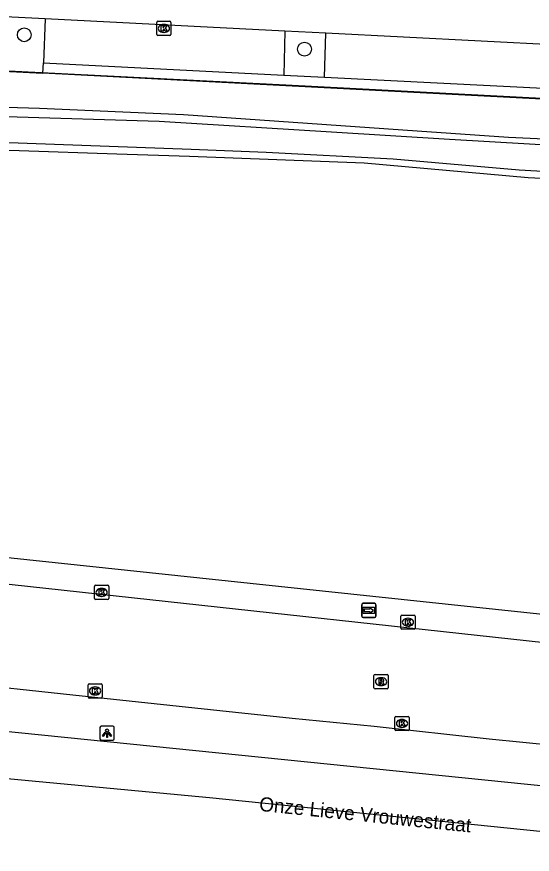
# Model space of a CAD drawing. Extents: x 161761 to 162722, y 384793 to 385405.
# Drawn here: x 162200.7 to 162237, y 384831.7 to 384890.8 of the extents above; entities that cross this region are included whole.
import ezdxf

# ---------------------------------------------------------------- set-up
doc = ezdxf.new("R2010")
doc.units = 0
for name, color, linetype in [('IMGEO_Boom', 7, 'Continuous'), ('IMGEO_Groenvoorziening', 7, 'Continuous'), ('IMGEO_Hek', 7, 'Continuous'), ('IMGEO_Kolk', 7, 'Continuous'), ('IMGEO_Lichtpunt', 7, 'Continuous'), ('IMGEO_Openbare_ruimte_label', 7, 'Continuous'), ('IMGEO_Parkeervlak_open', 7, 'Continuous'), ('IMGEO_Rijbaan_lokaal_open', 7, 'Continuous'), ('IMGEO_Rijbaan_regionaal_gesloten', 7, 'Continuous'), ('IMGEO_Rioolput', 7, 'Continuous'), ('IMGEO_Voetpad_open', 7, 'Continuous'), ('IMGEO_Waterloop', 7, 'Continuous'), ('IMGEO_Wegwijzer', 7, 'Continuous')]:
    doc.layers.add(name, color=color, linetype=linetype)

msp = doc.modelspace()

# ---------------------------------------------------------------- linework, layer by layer
at = {"layer": 'IMGEO_Boom'}
for centre in [(162201.199, 384889.51), (162220.962, 384888.492)]:
    msp.add_circle(centre, 0.489, dxfattribs=at)
at = {"layer": 'IMGEO_Groenvoorziening'}
for points in [[(162202.512, 384886.81), (162202.549, 384887.54)], [(162199.714, 384886.951), (162202.512, 384886.81)], [(162252.154, 384884.215), (162202.512, 384886.81)], [(162219.5, 384886.656), (162222.369, 384886.527)], [(162248.554, 384881.672), (162249.962, 384881.466), (162250.32, 384880.598), (162250.275, 384880.55), (162250.287, 384880.144), (162250.307, 384879.464), (162249.414, 384879.031), (162246.63, 384878.91), (162236.754, 384879.403), (162225.179, 384880.444), (162212.852, 384880.929), (162207.717, 384881.092), (162200.834, 384881.31), (162198.516, 384881.379), (162197.714, 384882.949), (162198.335, 384884.441), (162202.271, 384884.337), (162212.44, 384883.884), (162228.906, 384882.734), (162235.349, 384882.284), (162248.554, 384881.672)]]:
    msp.add_lwpolyline(points, dxfattribs=at)
at = {"layer": 'IMGEO_Hek'}
msp.add_lwpolyline([(162258.888, 384883.891), (162251.255, 384884.258), (162238.15, 384884.995), (162219.659, 384885.946), (162197.738, 384887.05), (162195.591, 384887.165), (162180.15, 384887.964)], dxfattribs=at)
at = {"layer": 'IMGEO_Kolk'}
for p, q in [((162210.545, 384889.533), (162210.545, 384890.385)), ((162210.62, 384890.459), (162211.472, 384890.459)), ((162211.546, 384890.385), (162211.546, 384889.533)), ((162211.033, 384890.239), (162211.058, 384890.239)), ((162211.472, 384889.459), (162210.62, 384889.459)), ((162211.056, 384889.679), (162211.031, 384889.679)), ((162206.154, 384849.734), (162206.154, 384850.586)), ((162206.229, 384850.66), (162207.081, 384850.66)), ((162206.642, 384850.44), (162206.667, 384850.44)), ((162207.155, 384850.586), (162207.155, 384849.734)), ((162207.081, 384849.66), (162206.229, 384849.66)), ((162206.665, 384849.88), (162206.64, 384849.88)), ((162227.764, 384847.634), (162227.764, 384848.486)), ((162227.839, 384848.56), (162228.691, 384848.56)), ((162228.765, 384848.486), (162228.765, 384847.634)), ((162228.252, 384848.34), (162228.277, 384848.34)), ((162228.691, 384847.56), (162227.839, 384847.56)), ((162228.275, 384847.78), (162228.25, 384847.78)), ((162205.773, 384843.707), (162206.625, 384843.707)), ((162205.698, 384842.781), (162205.698, 384843.633)), ((162206.186, 384843.487), (162206.211, 384843.487)), ((162206.699, 384843.633), (162206.699, 384842.781)), ((162206.625, 384842.707), (162205.773, 384842.707)), ((162206.209, 384842.927), (162206.184, 384842.927)), ((162227.345, 384840.486), (162227.345, 384841.338)), ((162227.42, 384841.412), (162228.272, 384841.412)), ((162228.346, 384841.338), (162228.346, 384840.486)), ((162227.833, 384841.192), (162227.858, 384841.192)), ((162228.272, 384840.412), (162227.42, 384840.412)), ((162227.856, 384840.632), (162227.831, 384840.632))]:
    msp.add_line(p, q, dxfattribs=at)
for points in [[(162210.545, 384889.533), (162210.545, 384890.385)], [(162210.62, 384890.459), (162211.472, 384890.459)], [(162211.546, 384890.385), (162211.546, 384889.533)], [(162210.866, 384890.159), (162210.989, 384890.159), (162210.989, 384890.008), (162211.119, 384890.159), (162211.283, 384890.159), (162211.137, 384890.008), (162211.29, 384889.759), (162211.138, 384889.759), (162211.053, 384889.923), (162210.989, 384889.856), (162210.989, 384889.759), (162210.866, 384889.759), (162210.866, 384890.159)], [(162211.472, 384889.459), (162210.62, 384889.459)], [(162206.154, 384849.734), (162206.154, 384850.586)], [(162206.229, 384850.66), (162207.081, 384850.66)], [(162206.475, 384850.36), (162206.598, 384850.36), (162206.598, 384850.209), (162206.728, 384850.36), (162206.892, 384850.36), (162206.746, 384850.209), (162206.899, 384849.96), (162206.747, 384849.96), (162206.662, 384850.124), (162206.598, 384850.057), (162206.598, 384849.96), (162206.475, 384849.96), (162206.475, 384850.36)], [(162207.155, 384850.586), (162207.155, 384849.734)], [(162207.081, 384849.66), (162206.229, 384849.66)], [(162227.764, 384847.634), (162227.764, 384848.486)], [(162227.839, 384848.56), (162228.691, 384848.56)], [(162228.765, 384848.486), (162228.765, 384847.634)], [(162228.085, 384848.26), (162228.208, 384848.26), (162228.208, 384848.109), (162228.338, 384848.26), (162228.502, 384848.26), (162228.356, 384848.109), (162228.509, 384847.86), (162228.357, 384847.86), (162228.272, 384848.024), (162228.208, 384847.957), (162228.208, 384847.86), (162228.085, 384847.86), (162228.085, 384848.26)], [(162228.691, 384847.56), (162227.839, 384847.56)], [(162205.773, 384843.707), (162206.625, 384843.707)], [(162205.698, 384842.781), (162205.698, 384843.633)], [(162206.019, 384843.407), (162206.142, 384843.407), (162206.142, 384843.256), (162206.272, 384843.407), (162206.436, 384843.407), (162206.29, 384843.256), (162206.443, 384843.007), (162206.291, 384843.007), (162206.206, 384843.171), (162206.142, 384843.104), (162206.142, 384843.007), (162206.019, 384843.007), (162206.019, 384843.407)], [(162206.699, 384843.633), (162206.699, 384842.781)], [(162206.625, 384842.707), (162205.773, 384842.707)], [(162227.345, 384840.486), (162227.345, 384841.338)], [(162227.42, 384841.412), (162228.272, 384841.412)], [(162228.346, 384841.338), (162228.346, 384840.486)], [(162227.666, 384841.112), (162227.789, 384841.112), (162227.789, 384840.961), (162227.919, 384841.112), (162228.083, 384841.112), (162227.937, 384840.961), (162228.09, 384840.712), (162227.938, 384840.712), (162227.853, 384840.876), (162227.789, 384840.809), (162227.789, 384840.712), (162227.666, 384840.712), (162227.666, 384841.112)], [(162228.272, 384840.412), (162227.42, 384840.412)]]:
    msp.add_lwpolyline(points, dxfattribs=at)
for centre, start, end in [((162210.622, 384890.383), 91.55205, 178.44795), ((162210.622, 384890.383), 91.55205, 178.44795), ((162211.47, 384890.383), 1.55205, 88.44795), ((162211.47, 384890.383), 1.55205, 88.44795), ((162210.622, 384889.535), 181.55205, 268.44795), ((162210.622, 384889.535), 181.55205, 268.44795), ((162211.47, 384889.535), 271.55205, 358.44795), ((162211.47, 384889.535), 271.55205, 358.44795), ((162206.231, 384850.584), 91.55205, 178.44795), ((162206.231, 384850.584), 91.55205, 178.44795), ((162207.079, 384850.584), 1.55205, 88.44795), ((162207.079, 384850.584), 1.55205, 88.44795), ((162206.231, 384849.736), 181.55205, 268.44795), ((162206.231, 384849.736), 181.55205, 268.44795), ((162207.079, 384849.736), 271.55205, 358.44795), ((162207.079, 384849.736), 271.55205, 358.44795), ((162227.841, 384848.484), 91.55205, 178.44795), ((162227.841, 384848.484), 91.55205, 178.44795), ((162228.689, 384848.484), 1.55205, 88.44795), ((162228.689, 384848.484), 1.55205, 88.44795), ((162227.841, 384847.636), 181.55205, 268.44795), ((162227.841, 384847.636), 181.55205, 268.44795), ((162228.689, 384847.636), 271.55205, 358.44795), ((162228.689, 384847.636), 271.55205, 358.44795), ((162205.775, 384843.631), 91.55205, 178.44795), ((162205.775, 384843.631), 91.55205, 178.44795), ((162206.623, 384843.631), 1.55205, 88.44795), ((162206.623, 384843.631), 1.55205, 88.44795), ((162205.775, 384842.783), 181.55205, 268.44795), ((162205.775, 384842.783), 181.55205, 268.44795), ((162206.623, 384842.783), 271.55205, 358.44795), ((162206.623, 384842.783), 271.55205, 358.44795), ((162227.422, 384841.336), 91.55205, 178.44795), ((162227.422, 384841.336), 91.55205, 178.44795), ((162228.27, 384841.336), 1.55205, 88.44795), ((162228.27, 384841.336), 1.55205, 88.44795), ((162227.422, 384840.488), 181.55205, 268.44795), ((162227.422, 384840.488), 181.55205, 268.44795), ((162228.27, 384840.488), 271.55205, 358.44795), ((162228.27, 384840.488), 271.55205, 358.44795)]:
    msp.add_arc(centre, 0.0765, start, end, dxfattribs=at)
for centre, major_axis, ratio, start_param, end_param in [((162211.032, 384889.959), (-0.387, 0.002), 0.722429, 4.712389, 7.853982), ((162211.057, 384889.959), (-0.39, 0.002), 0.717154, 1.570796, 4.712389), ((162206.641, 384850.16), (-0.387, 0.002), 0.722429, 4.712389, 7.853982), ((162206.666, 384850.16), (-0.39, 0.002), 0.717154, 1.570796, 4.712389), ((162228.251, 384848.06), (-0.387, 0.002), 0.722429, 4.712389, 7.853982), ((162228.276, 384848.06), (-0.39, 0.002), 0.717154, 1.570796, 4.712389), ((162206.185, 384843.207), (-0.387, 0.002), 0.722429, 4.712389, 7.853982), ((162206.21, 384843.207), (-0.39, 0.002), 0.717154, 1.570796, 4.712389), ((162227.832, 384840.912), (-0.387, 0.002), 0.722429, 4.712389, 7.853982), ((162227.857, 384840.912), (-0.39, 0.002), 0.717154, 1.570796, 4.712389)]:
    msp.add_ellipse(centre, major_axis=major_axis, ratio=ratio, start_param=start_param, end_param=end_param, dxfattribs=at)
at = {"layer": 'IMGEO_Lichtpunt'}
for p, q in [((162207.441, 384840.723), (162206.633, 384840.723)), ((162207.441, 384840.723), (162206.633, 384840.723)), ((162206.539, 384840.628), (162206.539, 384839.821)), ((162206.539, 384840.628), (162206.539, 384839.821)), ((162207.535, 384839.821), (162207.535, 384840.628)), ((162207.535, 384839.821), (162207.535, 384840.628)), ((162206.633, 384839.727), (162207.441, 384839.727)), ((162206.633, 384839.727), (162207.441, 384839.727))]:
    msp.add_line(p, q, dxfattribs=at)
for points in [[(162206.913, 384840.292), (162206.952, 384840.264), (162206.764, 384840.002), (162206.726, 384840.029), (162206.913, 384840.292)], [(162207.015, 384840.244), (162207.062, 384840.244), (162207.062, 384839.922), (162207.015, 384839.922), (162207.015, 384840.244)], [(162207.125, 384840.264), (162207.163, 384840.291), (162207.35, 384840.029), (162207.311, 384840.001), (162207.125, 384840.264)]]:
    msp.add_lwpolyline(points, dxfattribs=at)
msp.add_circle((162207.038, 384840.426), 0.0994, dxfattribs=at)
for centre, start, end in [((162206.633, 384840.628), 90, 180), ((162206.633, 384840.628), 90, 180), ((162207.441, 384840.628), 0, 90), ((162207.441, 384840.628), 0, 90), ((162206.633, 384839.821), 180, 270), ((162206.633, 384839.821), 180, 270), ((162207.441, 384839.821), 270, 0), ((162207.441, 384839.821), 270, 360)]:
    msp.add_arc(centre, 0.0946, start, end, dxfattribs=at)
at = {"layer": 'IMGEO_Parkeervlak_open'}
for points in [[(162202.684, 384890.636), (162202.549, 384887.54)], [(162219.571, 384889.76), (162219.5, 384886.656)], [(162222.369, 384886.527), (162222.476, 384889.62)], [(162202.549, 384887.54), (162219.5, 384886.656)], [(162222.369, 384886.527), (162238.747, 384885.688)]]:
    msp.add_lwpolyline(points, dxfattribs=at)
at = {"layer": 'IMGEO_Rijbaan_lokaal_open'}
for points in [[(162202.684, 384890.636), (162199.851, 384890.78)], [(162219.571, 384889.76), (162202.684, 384890.636)], [(162222.476, 384889.62), (162219.571, 384889.76)], [(162238.903, 384888.786), (162222.476, 384889.62)], [(162248.91, 384845.406), (162196.657, 384851.104), (162193.185, 384851.432), (162189.662, 384851.764), (162186.438, 384852.069), (162180.669, 384852.613), (162179.371, 384852.762), (162173.734, 384853.372), (162172.558, 384853.51), (162145.258, 384856.454), (162132.687, 384857.788)], [(162121.361, 384851.862), (162140.223, 384849.851), (162156.076, 384848.057), (162169.888, 384846.605), (162176.537, 384845.917), (162196.294, 384843.825), (162204.623, 384842.922), (162216.103, 384841.703), (162220.098, 384841.298), (162225.879, 384840.718), (162233.995, 384839.83), (162238.742, 384839.348), (162246.186, 384838.478), (162253.954, 384837.702), (162266.874, 384836.344)]]:
    msp.add_lwpolyline(points, dxfattribs=at)
at = {"layer": 'IMGEO_Rijbaan_regionaal_gesloten'}
for points in [[(162121.052, 384848.339), (162185.929, 384841.772), (162187.436, 384841.619), (162189.251, 384841.435), (162192.767, 384841.08), (162194.3, 384840.925), (162196.141, 384840.739), (162261.713, 384834.101), (162291.726, 384830.473), (162298.135, 384829.505), (162306.89, 384828.091), (162315.827, 384826.441), (162321.473, 384825.346), (162350.99, 384818.894), (162380.078, 384810.862), (162402.695, 384803.51)], [(162400.805, 384800.643), (162391.579, 384803.612), (162377.182, 384808.313), (162372.661, 384809.573), (162364.985, 384811.713), (162351.687, 384815.264), (162339.29, 384818.314), (162319.694, 384822.315), (162308.096, 384824.465), (162293.698, 384826.815), (162282.25, 384828.516), (162270.053, 384829.916), (162257.705, 384831.166), (162237.809, 384833.267), (162214.263, 384835.667), (162195.974, 384837.38)]]:
    msp.add_lwpolyline(points, dxfattribs=at)
at = {"layer": 'IMGEO_Rioolput'}
for p, q in [((162225.867, 384843.436), (162225.867, 384844.288)), ((162225.942, 384844.362), (162226.794, 384844.362)), ((162226.868, 384844.288), (162226.868, 384843.436)), ((162226.355, 384844.142), (162226.38, 384844.142)), ((162226.794, 384843.362), (162225.942, 384843.362)), ((162226.378, 384843.582), (162226.353, 384843.582))]:
    msp.add_line(p, q, dxfattribs=at)
for points in [[(162225.867, 384843.436), (162225.867, 384844.288)], [(162225.942, 384844.362), (162226.794, 384844.362)], [(162226.868, 384844.288), (162226.868, 384843.436)], [(162226.456, 384844.06), (162226.204, 384844.062), (162226.204, 384843.662)], [(162226.204, 384843.662), (162226.328, 384843.662), (162226.328, 384843.824), (162226.339, 384843.824)], [(162226.382, 384843.981), (162226.328, 384843.981), (162226.328, 384843.9)], [(162226.328, 384843.9), (162226.38, 384843.9)], [(162226.386, 384843.795), (162226.457, 384843.662), (162226.597, 384843.662), (162226.532, 384843.788)], [(162226.794, 384843.362), (162225.942, 384843.362)]]:
    msp.add_lwpolyline(points, dxfattribs=at)
for centre, radius, start, end in [((162225.944, 384844.286), 0.0765, 91.55205, 178.44795), ((162225.944, 384844.286), 0.0765, 91.55205, 178.44795), ((162226.792, 384844.286), 0.0765, 1.55205, 88.44795), ((162226.792, 384844.286), 0.0765, 1.55205, 88.44795), ((162226.338, 384843.771), 0.0533, 26.02933, 88.69889), ((162226.364, 384844.089), 0.19, 274.7715, 282.96867), ((162226.388, 384843.885), 0.0964, 77.00612, 93.18647), ((162226.402, 384843.942), 0.0378, 276.66336, 79.67722), ((162226.455, 384843.95), 0.109, 350.36119, 89.41601), ((162226.453, 384843.95), 0.112, 277.58423, 350.98172), ((162226.437, 384843.735), 0.108, 29.51342, 73.79051), ((162225.944, 384843.438), 0.0765, 181.55205, 268.44795), ((162225.944, 384843.438), 0.0765, 181.55205, 268.44795), ((162226.792, 384843.438), 0.0765, 271.55205, 358.44795), ((162226.792, 384843.438), 0.0765, 271.55205, 358.44795)]:
    msp.add_arc(centre, radius, start, end, dxfattribs=at)
for centre, major_axis, ratio, start_param, end_param in [((162226.354, 384843.862), (-0.387, 0.002), 0.722429, 4.712389, 7.853982), ((162226.379, 384843.862), (-0.39, 0.002), 0.717154, 1.570796, 4.712389)]:
    msp.add_ellipse(centre, major_axis=major_axis, ratio=ratio, start_param=start_param, end_param=end_param, dxfattribs=at)
at = {"layer": 'IMGEO_Voetpad_open'}
msp.add_lwpolyline([(162199.818, 384852.651), (162250.191, 384847.307)], dxfattribs=at)
at = {"layer": 'IMGEO_Waterloop'}
msp.add_lwpolyline([(162249.159, 384881.113), (162249.708, 384881.017), (162249.74, 384880.219), (162249.762, 384879.675), (162249.077, 384879.291), (162246.446, 384879.373), (162236.106, 384879.963), (162227.226, 384880.731), (162218.265, 384881.211), (162212.961, 384881.405), (162199.442, 384881.898), (162199.207, 384882.394), (162199.221, 384883.098), (162199.925, 384883.746), (162210.709, 384883.417), (162222.863, 384882.665), (162231.188, 384882.151), (162244.911, 384881.331), (162249.159, 384881.113)], dxfattribs=at)
at = {"layer": 'IMGEO_Wegwijzer'}
for p, q in [((162225.01, 384848.493), (162225.01, 384849.293)), ((162225.01, 384849.293), (162225.01, 384848.493)), ((162225.11, 384849.393), (162225.9, 384849.393)), ((162225.9, 384849.393), (162225.11, 384849.393)), ((162226, 384849.293), (162226, 384848.493)), ((162226, 384848.493), (162226, 384849.293)), ((162225.9, 384848.393), (162225.11, 384848.393)), ((162225.11, 384848.393), (162225.9, 384848.393))]:
    msp.add_line(p, q, dxfattribs=at)
for points in [[(162225.111, 384849.125), (162225.899, 384849.125), (162225.899, 384848.661), (162225.111, 384848.661), (162225.111, 384849.125)], [(162225.176, 384848.977), (162225.176, 384848.893), (162225.176, 384848.809), (162225.587, 384848.809), (162225.587, 384848.726), (162225.834, 384848.893), (162225.587, 384849.06), (162225.587, 384848.977), (162225.176, 384848.977)]]:
    msp.add_lwpolyline(points, dxfattribs=at)
for centre, start, end in [((162225.11, 384849.293), 90, 180), ((162225.11, 384849.293), 90, 180), ((162225.9, 384849.293), 0, 90), ((162225.9, 384849.293), 360, 90), ((162225.11, 384848.493), 180, 270), ((162225.11, 384848.493), 180, 270), ((162225.9, 384848.493), 270, 0), ((162225.9, 384848.493), 270, 0)]:
    msp.add_arc(centre, 0.1, start, end, dxfattribs=at)

# ---------------------------------------------------------------- texts
at = {"layer": 'IMGEO_Openbare_ruimte_label'}
msp.add_text('Onze Lieve Vrouwestraat', height=1, rotation=354.14691, dxfattribs=at).set_placement((162217.735, 384834.751))

doc.saveas('drawing.dxf')
